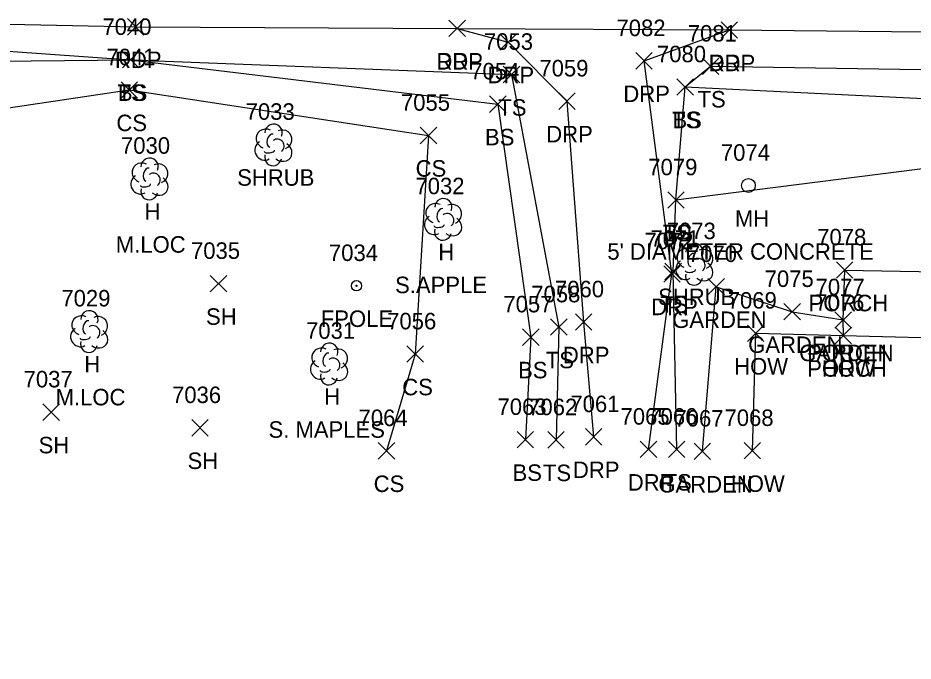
# Model space of a CAD drawing. Extents: x 1443912 to 1445411, y 621446 to 623693.
# Drawn here: x 1445132.2 to 1445240.8, y 622489.4 to 622567.4 of the extents above; entities that cross this region are included whole.
import ezdxf

# ---------------------------------------------------------------- set-up
doc = ezdxf.new("R2010")
doc.units = 0
for name, color, linetype in [('L_A', 7, 'Continuous'), ('L_C', 7, 'Continuous'), ('L_I', 7, 'Continuous'), ('L_TIC', 7, 'Continuous'), ('LAPB', 7, 'Continuous'), ('LBC', 7, 'Continuous'), ('LBF', 7, 'Continuous'), ('LELB', 7, 'Continuous'), ('LFP', 7, 'Continuous'), ('LSH', 7, 'Continuous'), ('LTD', 7, 'Continuous'), ('P_A', 7, 'Continuous'), ('P_TIC', 7, 'Continuous'), ('PET', 7, 'Continuous'), ('R_A', 7, 'Continuous'), ('R_I', 7, 'Continuous'), ('R_TIC', 7, 'Continuous'), ('RDP', 7, 'Continuous'), ('U_A', 7, 'Continuous'), ('U_C', 7, 'Continuous'), ('U_I', 7, 'Continuous'), ('UUMH', 7, 'Continuous')]:
    doc.layers.add(name, color=color, linetype=linetype)

msp = doc.modelspace()

# ---------------------------------------------------------------- linework, layer by layer
at = {"layer": 'L_TIC'}
for points in [[(1445144.89, 622561.33), (1445146.89, 622563.33)], [(1445146.89, 622561.33), (1445144.89, 622563.33)], [(1445144.89, 622561.33), (1445146.89, 622563.33)], [(1445146.89, 622561.33), (1445144.89, 622563.33)], [(1445215.23, 622560.53), (1445217.23, 622562.53)], [(1445217.23, 622560.53), (1445215.23, 622562.53)], [(1445191.07, 622559.53), (1445193.07, 622561.53)], [(1445193.07, 622559.53), (1445191.07, 622561.53)], [(1445212.14, 622558.02), (1445214.14, 622560.02)], [(1445214.14, 622558.02), (1445212.14, 622560.02)], [(1445212.14, 622558.02), (1445214.14, 622560.02)], [(1445214.14, 622558.02), (1445212.14, 622560.02)], [(1445144.72, 622557.66), (1445146.72, 622559.66)], [(1445146.72, 622557.66), (1445144.72, 622559.66)], [(1445189.42, 622555.94), (1445191.42, 622557.94)], [(1445191.42, 622555.94), (1445189.42, 622557.94)], [(1445181.01, 622552.14), (1445183.01, 622554.14)], [(1445183.01, 622552.14), (1445181.01, 622554.14)], [(1445211.02, 622544.31), (1445213.02, 622546.31)], [(1445213.02, 622544.31), (1445211.02, 622546.31)], [(1445211.02, 622544.31), (1445213.02, 622546.31)], [(1445213.02, 622544.31), (1445211.02, 622546.31)], [(1445210.69, 622535.63), (1445212.69, 622537.63)], [(1445212.69, 622535.63), (1445210.69, 622537.63)], [(1445231.49, 622535.81), (1445233.49, 622537.81)], [(1445233.49, 622535.81), (1445231.49, 622537.81)], [(1445155.55, 622534.17), (1445157.55, 622536.17)], [(1445157.55, 622534.17), (1445155.55, 622536.17)], [(1445215.9, 622533.79), (1445217.9, 622535.79)], [(1445217.9, 622533.79), (1445215.9, 622535.79)], [(1445225.11, 622530.76), (1445227.11, 622532.76)], [(1445227.11, 622530.76), (1445225.11, 622532.76)], [(1445231.3, 622529.76), (1445233.3, 622531.76)], [(1445233.3, 622529.76), (1445231.3, 622531.76)], [(1445231.3, 622529.76), (1445233.3, 622531.76)], [(1445233.3, 622529.76), (1445231.3, 622531.76)], [(1445196.82, 622528.9), (1445198.82, 622530.9)], [(1445198.82, 622528.9), (1445196.82, 622530.9)], [(1445193.43, 622527.68), (1445195.43, 622529.68)], [(1445195.43, 622527.68), (1445193.43, 622529.68)], [(1445220.69, 622528.14), (1445222.69, 622530.14)], [(1445222.69, 622528.14), (1445220.69, 622530.14)], [(1445231.32, 622527.88), (1445233.32, 622529.88)], [(1445233.32, 622527.88), (1445231.32, 622529.88)], [(1445231.32, 622527.88), (1445233.32, 622529.88)], [(1445233.32, 622527.88), (1445231.32, 622529.88)], [(1445179.39, 622525.62), (1445181.39, 622527.62)], [(1445181.39, 622525.62), (1445179.39, 622527.62)], [(1445135.25, 622518.58), (1445137.25, 622520.58)], [(1445137.25, 622518.58), (1445135.25, 622520.58)], [(1445153.3, 622516.68), (1445155.3, 622518.68)], [(1445155.3, 622516.68), (1445153.3, 622518.68)], [(1445192.76, 622515.24), (1445194.76, 622517.24)], [(1445194.76, 622515.24), (1445192.76, 622517.24)], [(1445196.48, 622515.21), (1445198.48, 622517.21)], [(1445198.48, 622515.21), (1445196.48, 622517.21)], [(1445175.92, 622513.89), (1445177.92, 622515.89)], [(1445177.92, 622513.89), (1445175.92, 622515.89)], [(1445211.11, 622514.06), (1445213.11, 622516.06)], [(1445213.11, 622514.06), (1445211.11, 622516.06)], [(1445214.22, 622513.83), (1445216.22, 622515.83)], [(1445216.22, 622513.83), (1445214.22, 622515.83)], [(1445220.29, 622513.9), (1445222.29, 622515.9)], [(1445222.29, 622513.9), (1445220.29, 622515.9)]]:
    msp.add_lwpolyline(points, dxfattribs=at)
at = {"layer": 'LAPB'}
msp.add_lwpolyline([(1445215.22, 622514.83), (1445216.9, 622534.79), (1445226.11, 622531.76), (1445232.3, 622530.76)], dxfattribs=at)
at = {"layer": 'LBC'}
msp.add_lwpolyline([(1445221.29, 622514.9), (1445221.69, 622529.14), (1445232.32, 622528.88), (1445248.05, 622528.46), (1445258.39, 622528.16), (1445257.64, 622499.39)], dxfattribs=at)
at = {"layer": 'LBF'}
msp.add_lwpolyline([(1445232.32, 622528.88), (1445232.3, 622530.76), (1445232.49, 622536.81), (1445248.18, 622536.5), (1445248.05, 622528.46)], dxfattribs=at)
at = {"layer": 'LELB'}
for points in [[(1445012.51, 622489.38), (1445021.59, 622519.19), (1445030.11, 622546.89), (1445027.27, 622559.74), (1445039.74, 622563.96), (1445055.31, 622565.96), (1445105.9, 622565.16), (1445145.89, 622562.33), (1445190.42, 622556.94), (1445194.43, 622528.68), (1445193.76, 622516.24)], [(1445012.51, 622489.38), (1445013.85, 622519.65), (1445021.11, 622546.77), (1445018.51, 622560.52), (1445028.35, 622564.05), (1445039.74, 622563.96), (1445054.56, 622562.54), (1445105.74, 622561.89), (1445145.89, 622562.33), (1445192.07, 622560.53), (1445197.82, 622529.9), (1445197.48, 622516.21)], [(1445212.11, 622515.06), (1445211.69, 622536.63), (1445212.02, 622545.31), (1445213.14, 622559.02), (1445216.23, 622561.53), (1445249.37, 622561.02), (1445284.75, 622559.81), (1445309.63, 622554.18), (1445329.89, 622553.21), (1445336.29, 622560.61), (1445337.53, 622548.37), (1445337.66, 622516.12)], [(1445213.14, 622559.02), (1445249.48, 622557.26), (1445283.95, 622556.67), (1445310.29, 622550.56), (1445332.98, 622548.64), (1445336.29, 622560.61), (1445343.12, 622550.15), (1445346.83, 622516.65)], [(1445036.26, 622511.31), (1445043.47, 622532.24), (1445069.86, 622548.49), (1445102.85, 622552.3), (1445145.72, 622558.66), (1445182.01, 622553.14), (1445180.39, 622526.62), (1445176.92, 622514.89)], [(1445212.02, 622545.31), (1445248.9, 622550.03), (1445279.24, 622548.37), (1445284.33, 622544.82), (1445283.55, 622531.56), (1445285.97, 622514.53)]]:
    msp.add_lwpolyline(points, dxfattribs=at)
at = {"layer": 'LFP'}
for radius in [0.625, 0.0833]:
    msp.add_circle((1445173.28, 622534.91), radius, dxfattribs=at)
at = {"layer": 'LSH'}
for p, q in [((1445163.18, 622552.04), (1445163.18, 622552.04)), ((1445163.18, 622552.04), (1445163.18, 622552.04)), ((1445214.23, 622537.56), (1445214.23, 622537.56)), ((1445214.23, 622537.56), (1445214.23, 622537.56))]:
    msp.add_line(p, q, dxfattribs=at)
for centre in [(1445163.23, 622553.47), (1445214.28, 622538.99)]:
    msp.add_arc(centre, 1.05, 335.5272, 180.9563, dxfattribs=at)
for centre, major_axis, ratio, start_param, end_param in [((1445162.39, 622552.71), (1.21, -0.51), 0.895232, 1.570796, 4.712389), ((1445162.97, 622552.5), (-0.208, -0.792), 0.645439, 3.141593, 6.283185), ((1445164.22, 622552.62), (-1.14, -0.48), 0.949671, 1.570796, 4.712389), ((1445162.1, 622551.33), (0.58, -1.04), 0.959034, 3.141593, 6.283185), ((1445163.68, 622551.87), (-0.5, 0.667), 0.989748, 3.141593, 6.283185), ((1445162.72, 622551.29), (-0.625, -0.083), 0.423636, 0, 3.141593), ((1445164.18, 622551.21), (-1.09, 0.79), 0.841452, 1.570796, 4.712389), ((1445163.18, 622550.54), (0.26, 1.06), 0.942809, 1.570796, 4.712389), ((1445213.44, 622538.23), (1.21, -0.51), 0.895232, 1.570796, 4.712389), ((1445215.28, 622538.14), (-1.14, -0.48), 0.949671, 1.570796, 4.712389), ((1445214.03, 622538.02), (-0.208, -0.792), 0.645439, 3.141593, 6.283185), ((1445214.73, 622537.39), (-0.5, 0.667), 0.989748, 3.141593, 6.283185), ((1445213.15, 622536.85), (0.58, -1.04), 0.959034, 3.141593, 6.283185), ((1445215.23, 622536.73), (-1.09, 0.79), 0.841452, 1.570796, 4.712389), ((1445214.23, 622536.06), (0.26, 1.06), 0.942809, 1.570796, 4.712389), ((1445213.78, 622536.81), (-0.625, -0.083), 0.423636, 0, 3.141593)]:
    msp.add_ellipse(centre, major_axis=major_axis, ratio=ratio, start_param=start_param, end_param=end_param, dxfattribs=at)
at = {"layer": 'LTD'}
for p, q in [((1445148.15, 622547.92), (1445148.15, 622547.92)), ((1445148.15, 622547.92), (1445148.15, 622547.92)), ((1445183.77, 622543.01), (1445183.77, 622543.01)), ((1445183.77, 622543.01), (1445183.77, 622543.01)), ((1445140.84, 622529.4), (1445140.84, 622529.4)), ((1445140.84, 622529.4), (1445140.84, 622529.4)), ((1445169.94, 622525.47), (1445169.94, 622525.47)), ((1445169.94, 622525.47), (1445169.94, 622525.47))]:
    msp.add_line(p, q, dxfattribs=at)
for centre in [(1445148.19, 622549.35), (1445183.81, 622544.44), (1445140.89, 622530.84), (1445169.98, 622526.9)]:
    msp.add_arc(centre, 1.05, 335.5272, 180.9563, dxfattribs=at)
for centre, major_axis, ratio, start_param, end_param in [((1445147.35, 622548.59), (1.21, -0.51), 0.895232, 1.570796, 4.712389), ((1445147.94, 622548.38), (-0.208, -0.792), 0.645439, 3.141593, 6.283185), ((1445149.19, 622548.5), (-1.14, -0.48), 0.949671, 1.570796, 4.712389), ((1445147.06, 622547.21), (0.58, -1.04), 0.959034, 3.141593, 6.283185), ((1445148.65, 622547.75), (-0.5, 0.667), 0.989748, 3.141593, 6.283185), ((1445149.15, 622547.09), (-1.09, 0.79), 0.841452, 1.570796, 4.712389), ((1445147.69, 622547.17), (-0.625, -0.083), 0.423636, 0, 3.141593), ((1445148.15, 622546.42), (0.26, 1.06), 0.942809, 1.570796, 4.712389), ((1445182.98, 622543.68), (1.21, -0.51), 0.895232, 1.570796, 4.712389), ((1445184.81, 622543.59), (-1.14, -0.48), 0.949671, 1.570796, 4.712389), ((1445183.56, 622543.47), (-0.208, -0.792), 0.645439, 3.141593, 6.283185), ((1445184.27, 622542.84), (-0.5, 0.667), 0.989748, 3.141593, 6.283185), ((1445182.68, 622542.3), (0.58, -1.04), 0.959034, 3.141593, 6.283185), ((1445184.77, 622542.18), (-1.09, 0.79), 0.841452, 1.570796, 4.712389), ((1445183.77, 622541.51), (0.26, 1.06), 0.942809, 1.570796, 4.712389), ((1445183.31, 622542.26), (-0.625, -0.083), 0.423636, 0, 3.141593), ((1445140.05, 622530.07), (1.21, -0.51), 0.895232, 1.570796, 4.712389), ((1445140.63, 622529.86), (-0.208, -0.792), 0.645439, 3.141593, 6.283185), ((1445141.88, 622529.99), (-1.14, -0.48), 0.949671, 1.570796, 4.712389), ((1445139.76, 622528.69), (0.58, -1.04), 0.959034, 3.141593, 6.283185), ((1445141.34, 622529.24), (-0.5, 0.667), 0.989748, 3.141593, 6.283185), ((1445141.84, 622528.57), (-1.09, 0.79), 0.841452, 1.570796, 4.712389), ((1445140.38, 622528.65), (-0.625, -0.083), 0.423636, 0, 3.141593), ((1445140.84, 622527.9), (0.26, 1.06), 0.942809, 1.570796, 4.712389), ((1445169.14, 622526.14), (1.21, -0.51), 0.895232, 1.570796, 4.712389), ((1445170.98, 622526.05), (-1.14, -0.48), 0.949671, 1.570796, 4.712389), ((1445169.73, 622525.93), (-0.208, -0.792), 0.645439, 3.141593, 6.283185), ((1445170.44, 622525.3), (-0.5, 0.667), 0.989748, 3.141593, 6.283185), ((1445168.85, 622524.76), (0.58, -1.04), 0.959034, 3.141593, 6.283185), ((1445170.94, 622524.64), (-1.09, 0.79), 0.841452, 1.570796, 4.712389), ((1445169.94, 622523.97), (0.26, 1.06), 0.942809, 1.570796, 4.712389), ((1445169.48, 622524.72), (-0.625, -0.083), 0.423636, 0, 3.141593)]:
    msp.add_ellipse(centre, major_axis=major_axis, ratio=ratio, start_param=start_param, end_param=end_param, dxfattribs=at)
at = {"layer": 'P_TIC'}
for points in [[(1445145.5, 622565.32), (1445147.5, 622567.32)], [(1445147.5, 622565.32), (1445145.5, 622567.32)], [(1445184.48, 622565.13), (1445186.48, 622567.13)], [(1445186.48, 622565.13), (1445184.48, 622567.13)], [(1445217.5, 622564.93), (1445219.5, 622566.93)], [(1445219.5, 622564.93), (1445217.5, 622566.93)]]:
    msp.add_lwpolyline(points, dxfattribs=at)
at = {"layer": 'PET'}
msp.add_lwpolyline([(1444762.32, 622550.87), (1444765.48, 622555.51), (1444771.42, 622562.4), (1444777.98, 622567.72), (1444778.97, 622567.88), (1444793.44, 622574.04), (1444804, 622575.78), (1444819.79, 622575.28), (1444849.9, 622575.24), (1444896.52, 622573.13), (1444944.4, 622570.43), (1444985.66, 622568.62), (1445016.28, 622568.79), (1445055.76, 622567.84), (1445106.1, 622567.18), (1445146.5, 622566.32), (1445185.48, 622566.13), (1445218.5, 622565.93), (1445249.94, 622565.64), (1445288.6, 622564.79), (1445341.53, 622564.99), (1445404.89, 622565.43)], dxfattribs=at)
at = {"layer": 'R_TIC'}
for points in [[(1445184.48, 622565.13), (1445186.48, 622567.13)], [(1445186.48, 622565.13), (1445184.48, 622567.13)], [(1445217.5, 622564.93), (1445219.5, 622566.93)], [(1445219.5, 622564.93), (1445217.5, 622566.93)], [(1445190.68, 622563.47), (1445192.68, 622565.47)], [(1445192.68, 622563.47), (1445190.68, 622565.47)], [(1445207.15, 622561.19), (1445209.15, 622563.19)], [(1445209.15, 622561.19), (1445207.15, 622563.19)], [(1445197.8, 622556.3), (1445199.8, 622558.3)], [(1445199.8, 622556.3), (1445197.8, 622558.3)], [(1445210.54, 622535.34), (1445212.54, 622537.34)], [(1445212.54, 622535.34), (1445210.54, 622537.34)], [(1445199.82, 622529.51), (1445201.82, 622531.51)], [(1445201.82, 622529.51), (1445199.82, 622531.51)], [(1445201.04, 622515.58), (1445203.04, 622517.58)], [(1445203.04, 622515.58), (1445201.04, 622517.58)], [(1445207.69, 622514.06), (1445209.69, 622516.06)], [(1445209.69, 622514.06), (1445207.69, 622516.06)]]:
    msp.add_lwpolyline(points, dxfattribs=at)
at = {"layer": 'RDP'}
for points in [[(1445185.48, 622566.13), (1445191.68, 622564.47), (1445198.8, 622557.3), (1445200.82, 622530.51), (1445202.04, 622516.58)], [(1445208.69, 622515.06), (1445211.54, 622536.34), (1445208.15, 622562.19), (1445218.5, 622565.93)]]:
    msp.add_lwpolyline(points, dxfattribs=at)
at = {"layer": 'UUMH'}
for p, q in [((1445220.8, 622547.07), (1445220.8, 622547.07)), ((1445221.64, 622547.07), (1445221.64, 622547.07))]:
    msp.add_line(p, q, dxfattribs=at)
msp.add_circle((1445220.8, 622547.07), 0.833, dxfattribs=at)

# ---------------------------------------------------------------- texts
at = {"layer": 'L_A'}
for s, p in [('TS', (1445144.3, 622557.33)), ('BS', (1445144.34, 622557.33)), ('TS', (1445214.64, 622556.53)), ('TS', (1445190.48, 622555.53)), ('CS', (1445144.16, 622553.66)), ('TS', (1445211.55, 622554.02)), ('BS', (1445211.59, 622554.02)), ('BS', (1445188.86, 622551.94)), ('CS', (1445180.45, 622548.14)), ('SHRUB', (1445158.81, 622547.04)), ('H', (1445147.58, 622542.92)), ('TS', (1445210.43, 622540.31)), ('BS', (1445210.46, 622540.31)), ('H', (1445183.2, 622538.01)), ('SHRUB', (1445209.86, 622532.56)), ('PORCH', (1445228.11, 622531.81)), ('TS', (1445210.1, 622531.63)), ('SH', (1445155.03, 622530.17)), ('FPOLE', (1445168.95, 622529.91)), ('GARDEN', (1445211.57, 622529.79)), ('GARDEN', (1445220.78, 622526.76)), ('GARDEN', (1445226.97, 622525.76)), ('PORCH', (1445227.92, 622525.76)), ('H', (1445140.27, 622524.4)), ('TS', (1445196.23, 622524.9)), ('HOW', (1445219.08, 622524.14)), ('BS', (1445192.87, 622523.68)), ('PORCH', (1445227.94, 622523.88)), ('HOW', (1445229.7, 622523.88)), ('CS', (1445178.83, 622521.62)), ('H', (1445169.37, 622520.47)), ('SH', (1445134.73, 622514.58)), ('SH', (1445152.79, 622512.68)), ('BS', (1445192.2, 622511.24)), ('TS', (1445195.89, 622511.21)), ('TS', (1445210.52, 622510.06)), ('CS', (1445175.36, 622509.89)), ('GARDEN', (1445209.89, 622509.83)), ('HOW', (1445218.68, 622509.9))]:
    msp.add_text(s, height=2, dxfattribs=at).set_placement(p)
at = {"layer": 'L_C'}
for s, p in [('M.LOC', (1445144.09, 622538.92)), ('S.APPLE', (1445177.96, 622534.01)), ('M.LOC', (1445136.79, 622520.4)), ('S. MAPLES', (1445162.61, 622516.47))]:
    msp.add_text(s, height=2, dxfattribs=at).set_placement(p)
at = {"layer": 'L_I'}
for s, p in [('7040', (1445142.47, 622565.33)), ('7040', (1445142.47, 622565.33)), ('7081', (1445213.46, 622564.53)), ('7053', (1445188.74, 622563.53)), ('7041', (1445142.95, 622561.66)), ('7080', (1445209.72, 622562.02)), ('7080', (1445209.72, 622562.02)), ('7054', (1445187.08, 622559.94)), ('7055', (1445178.67, 622556.14)), ('7033', (1445159.84, 622555.04)), ('7030', (1445144.72, 622550.92)), ('7079', (1445208.67, 622548.31)), ('7079', (1445208.67, 622548.31)), ('7032', (1445180.43, 622546.01)), ('7073', (1445210.9, 622540.56)), ('7071', (1445208.92, 622539.63)), ('7078', (1445229.15, 622539.81)), ('7035', (1445153.21, 622538.17)), ('7034', (1445169.94, 622537.91)), ('7070', (1445213.47, 622537.79)), ('7075', (1445222.78, 622534.76)), ('7058', (1445194.48, 622532.9)), ('7077', (1445228.96, 622533.76)), ('7077', (1445228.96, 622533.76)), ('7029', (1445137.49, 622532.4)), ('7069', (1445218.3, 622532.14)), ('7076', (1445228.92, 622531.88)), ('7076', (1445228.92, 622531.88)), ('7057', (1445191.09, 622531.68)), ('7056', (1445177, 622529.62)), ('7031', (1445167.16, 622528.47)), ('7037', (1445132.91, 622522.58)), ('7036', (1445150.91, 622520.68)), ('7063', (1445190.38, 622519.24)), ('7062', (1445194.1, 622519.21)), ('7064', (1445173.53, 622517.89)), ('7066', (1445208.67, 622518.06)), ('7067', (1445211.84, 622517.83)), ('7068', (1445217.91, 622517.9))]:
    msp.add_text(s, height=2, dxfattribs=at).set_placement(p)
at = {"layer": 'P_A'}
for p in [(1445143.99, 622561.32), (1445182.97, 622561.13), (1445215.99, 622560.93)]:
    msp.add_text('RDP', height=2, dxfattribs=at).set_placement(p)
at = {"layer": 'R_A'}
for p in [(1445182.97, 622561.13), (1445215.99, 622560.93), (1445189.17, 622559.47), (1445205.64, 622557.19), (1445196.29, 622552.3), (1445209.02, 622531.34), (1445198.31, 622525.51), (1445199.53, 622511.58), (1445206.18, 622510.06)]:
    msp.add_text('DRP', height=2, dxfattribs=at).set_placement(p)
at = {"layer": 'R_I'}
for s, p in [('7082', (1445204.81, 622565.19)), ('7059', (1445195.46, 622560.3)), ('7072', (1445208.2, 622539.34)), ('7060', (1445197.35, 622533.51)), ('7061', (1445199.22, 622519.58)), ('7065', (1445205.3, 622518.06))]:
    msp.add_text(s, height=2, dxfattribs=at).set_placement(p)
at = {"layer": 'U_A'}
msp.add_text('MH', height=2, dxfattribs=at).set_placement((1445219.17, 622542.07))
at = {"layer": 'U_C'}
msp.add_text("5' DIAMETER CONCRETE", height=2, dxfattribs=at).set_placement((1445203.7, 622538.07))
at = {"layer": 'U_I'}
msp.add_text('7074', height=2, dxfattribs=at).set_placement((1445217.47, 622550.07))

doc.saveas('drawing.dxf')
